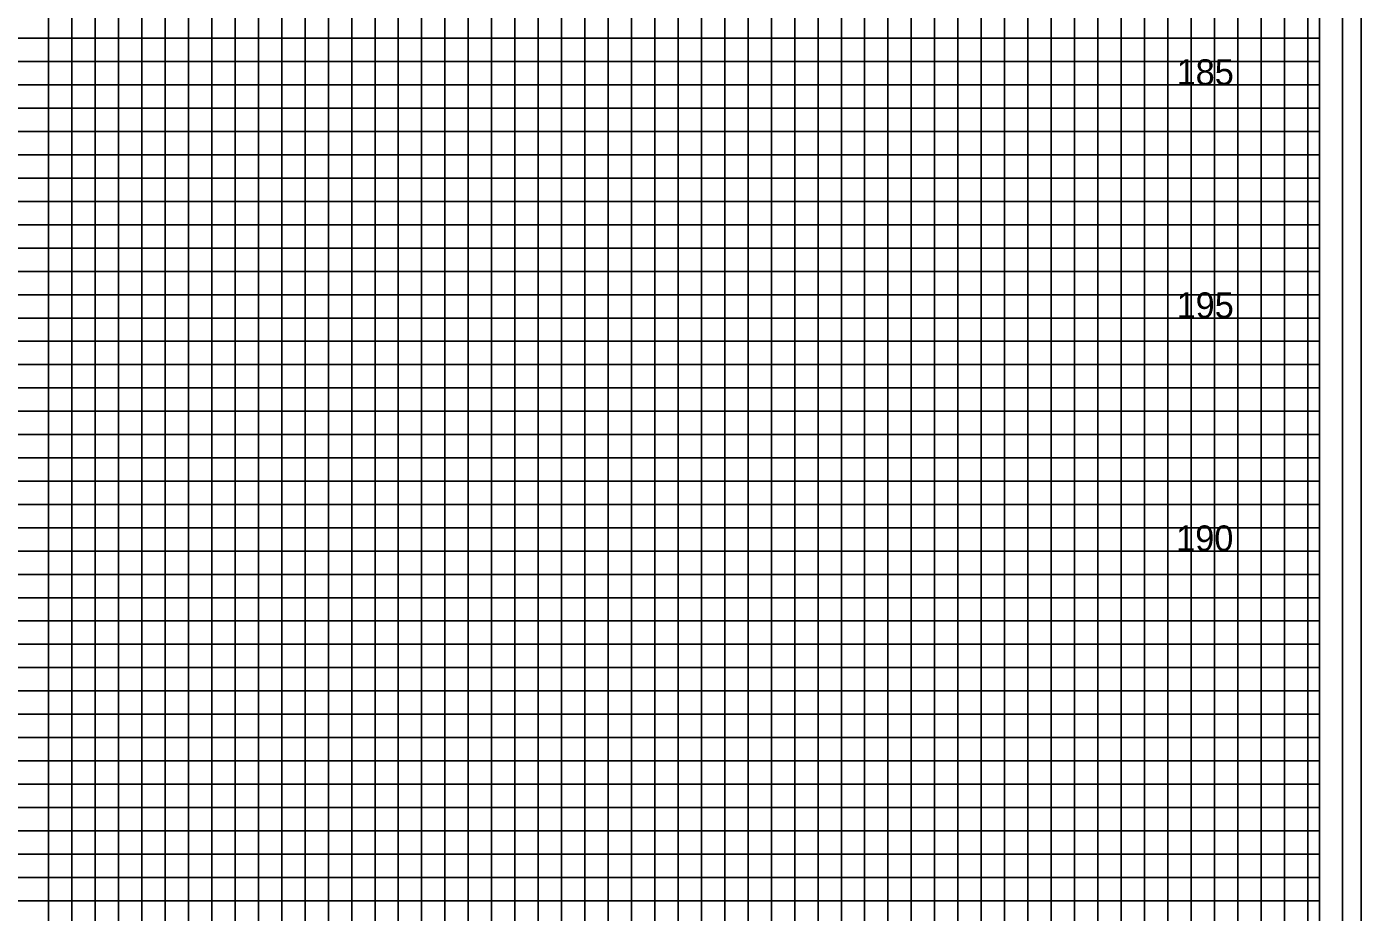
# Model space of a CAD drawing. Extents: x -4 to 103, y -2 to 138.
# Drawn here: x 74.78 to 103.4, y 32.25 to 51.25 of the extents above; entities that cross this region are included whole.
import ezdxf

# ---------------------------------------------------------------- set-up
doc = ezdxf.new("R2010")
doc.units = 0
for name, color, linetype in [('Old_Level_10', 7, 'Continuous'), ('Old_Level_4', 7, 'Continuous'), ('Old_Level_5', 7, 'Continuous'), ('Old_Level_8', 7, 'Continuous'), ('Prop Dimension', 7, 'Continuous'), ('Prop XS Finish Grade', 7, 'Continuous'), ('Prop XS SE Text', 7, 'Continuous')]:
    doc.layers.add(name, color=color, linetype=linetype)

msp = doc.modelspace()

# ---------------------------------------------------------------- linework, layer by layer
at = {"layer": 'Old_Level_10'}
for p, q in [((91.25, 0), (91.25, 63.425)), ((93.75, 0), (93.75, 63.425)), ((96.25, 0), (96.25, 63.425)), ((98.75, 0), (98.75, 63.425)), ((101.25, 0), (101.25, 63.425)), ((76.25, 0), (76.25, 62)), ((78.75, 0), (78.75, 62)), ((81.25, 0), (81.25, 62)), ((83.75, 0), (83.75, 62)), ((86.25, 0), (86.25, 62)), ((88.75, 0), (88.75, 62)), ((0, 50), (102.5, 50)), ((0, 47.5), (102.5, 47.5)), ((0, 45), (102.5, 45)), ((0, 42.5), (102.5, 42.5)), ((0, 40), (102.5, 40)), ((0, 37.5), (102.5, 37.5)), ((0, 35), (102.5, 35)), ((0, 32.5), (102.5, 32.5))]:
    msp.add_line(p, q, dxfattribs=at)
at = {"layer": 'Old_Level_4'}
msp.add_lwpolyline([(103, 66), (-2.8, 66), (-2.8, -1), (103, -1)], close=True, dxfattribs=at)
at = {"layer": 'Old_Level_5'}
msp.add_lwpolyline([(103.4, 67.4), (-3.5, 67.4), (-3.5, -2.425), (103.4, -2.425)], close=True, dxfattribs=at)
at = {"layer": 'Old_Level_8'}
for points in [[(91.25, 0), (91.25, 63.425), (93.75, 63.425), (93.75, 0)], [(96.25, 0), (96.25, 63.425), (98.75, 63.425), (98.75, 0)], [(101.25, 0), (101.25, 63.425)], [(76.25, 0), (76.25, 62), (78.75, 62), (78.75, 0)], [(81.25, 0), (81.25, 62), (83.75, 62), (83.75, 0)], [(86.25, 0), (86.25, 62), (88.75, 62), (88.75, 0)], [(0, 47.5), (102.5, 47.5), (102.5, 50), (0, 50)], [(0, 42.5), (102.5, 42.5), (102.5, 45), (0, 45)], [(0, 37.5), (102.5, 37.5), (102.5, 40), (0, 40)], [(0, 32.5), (102.5, 32.5), (102.5, 35), (0, 35)]]:
    msp.add_lwpolyline(points, dxfattribs=at)
at = {"layer": 'Prop Dimension'}
for points in [[(90.25, 0), (90.25, 63.425), (90.75, 63.425), (90.75, 0)], [(91.75, 0), (91.75, 63.425), (92.25, 63.425), (92.25, 0)], [(92.75, 0), (92.75, 63.425), (93.25, 63.425), (93.25, 0)], [(94.25, 0), (94.25, 63.425), (94.75, 63.425), (94.75, 0)], [(95.25, 0), (95.25, 63.425), (95.75, 63.425), (95.75, 0)], [(96.75, 0), (96.75, 63.425), (97.25, 63.425), (97.25, 0)], [(97.75, 0), (97.75, 63.425), (98.25, 63.425), (98.25, 0)], [(99.25, 0), (99.25, 63.425), (99.75, 63.425), (99.75, 0)], [(100.25, 0), (100.25, 63.425)], [(100.25, 63.425), (100.75, 63.425), (100.75, 0), (101.75, 0), (101.75, 63.425), (102.25, 63.425), (102.25, 0)], [(75.25, 0), (75.25, 62), (75.75, 62), (75.75, 0)], [(76.75, 0), (76.75, 62), (77.25, 62), (77.25, 0)], [(77.75, 0), (77.75, 62), (78.25, 62), (78.25, 0)], [(79.25, 0), (79.25, 62), (79.75, 62), (79.75, 0)], [(80.25, 0), (80.25, 62), (80.75, 62), (80.75, 0)], [(81.75, 0), (81.75, 62), (82.25, 62), (82.25, 0)], [(82.75, 0), (82.75, 62), (83.25, 62), (83.25, 0)], [(84.25, 0), (84.25, 62), (84.75, 62), (84.75, 0)], [(85.25, 0), (85.25, 62), (85.75, 62), (85.75, 0)], [(86.75, 0), (86.75, 62), (87.25, 62), (87.25, 0)], [(87.75, 0), (87.75, 62), (88.25, 62), (88.25, 0)], [(89.25, 0), (89.25, 62), (89.75, 62), (89.75, 0)], [(0, 50.5), (102.5, 50.5), (102.5, 51), (0, 51)], [(0, 49), (102.5, 49), (102.5, 49.5), (0, 49.5)], [(0, 48), (102.5, 48), (102.5, 48.5), (0, 48.5)], [(0, 46.5), (102.5, 46.5), (102.5, 47), (0, 47)], [(0, 45.5), (102.5, 45.5), (102.5, 46), (0, 46)], [(0, 44), (102.5, 44), (102.5, 44.5), (0, 44.5)], [(0, 43), (102.5, 43), (102.5, 43.5), (0, 43.5)], [(0, 41.5), (102.5, 41.5), (102.5, 42), (0, 42)], [(0, 40.5), (102.5, 40.5), (102.5, 41), (0, 41)], [(0, 39), (102.5, 39), (102.5, 39.5), (0, 39.5)], [(0, 38), (102.5, 38), (102.5, 38.5), (0, 38.5)], [(0, 36.5), (102.5, 36.5), (102.5, 37), (0, 37)], [(0, 35.5), (102.5, 35.5), (102.5, 36), (0, 36)], [(0, 34), (102.5, 34), (102.5, 34.5), (0, 34.5)], [(0, 33), (102.5, 33), (102.5, 33.5), (0, 33.5)]]:
    msp.add_lwpolyline(points, dxfattribs=at)
at = {"layer": 'Prop XS SE Text'}
msp.add_lwpolyline([(102.5, 65), (0, 65), (0, 0), (102.5, 0)], close=True, dxfattribs=at)

# ---------------------------------------------------------------- texts
at = {"layer": 'Prop XS Finish Grade'}
for s, p in [('185', (99.4383, 50)), ('195', (99.4383, 45)), ('190', (99.4296, 40))]:
    msp.add_text(s, height=0.55, dxfattribs=at).set_placement(p)

doc.saveas('drawing.dxf')
